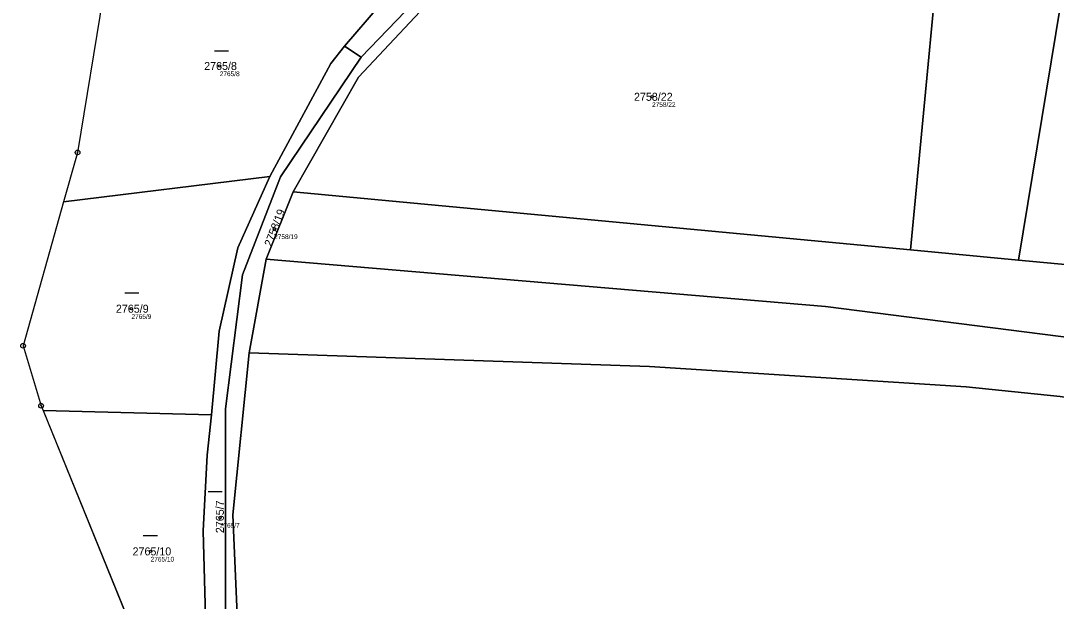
# Model space of a CAD drawing. Extents: x -739214 to -733252, y -1147612 to -1142842.
# Drawn here: x -738787.4 to -738567.4, y -1144355 to -1144231.8 of the extents above; entities that cross this region are included whole.
import ezdxf

# ---------------------------------------------------------------- set-up
doc = ezdxf.new("R2010")
doc.units = 0
for name, color, linetype in [('Definiční body', 7, 'Continuous'), ('Hranice parcel', 7, 'Continuous'), ('Parcelní čísla', 7, 'Continuous'), ('Polygon ku', 7, 'Continuous'), ('Polygon parcely', 7, 'Continuous'), ('Značky bodu BP', 7, 'Continuous'), ('Značky kultur', 7, 'Continuous')]:
    doc.layers.add(name, color=color, linetype=linetype)

msp = doc.modelspace()

# ---------------------------------------------------------------- linework, layer by layer
at = {"layer": 'Definiční body'}
for centre in [(-738745.09, -1144241.38), (-738653.27, -1144247.92), (-738733.53, -1144275.95), (-738763.84, -1144292.89), (-738745.07, -1144337.2), (-738759.77, -1144344.38)]:
    msp.add_circle(centre, 0.25, dxfattribs=at)
at = {"layer": 'Hranice parcel'}
for p, q in [((-738711.14, -1144228.53), (-738718.62, -1144237.17)), ((-738718.62, -1144237.17), (-738715.02, -1144239.51)), ((-738778.25, -1144270.22), (-738734.47, -1144264.86)), ((-738735.23, -1144282.35), (-738729.51, -1144268.12)), ((-738729.51, -1144268.12), (-738598.34, -1144280.41)), ((-738778.25, -1144270.22), (-738786.87, -1144300.76)), ((-738598.34, -1144280.41), (-738575.42, -1144282.56)), ((-738738.82, -1144302.23), (-738735.23, -1144282.35)), ((-738575.42, -1144282.56), (-738557.93, -1144284.19)), ((-738782.62, -1144314.52), (-738746.88, -1144315.43)), ((-738782.62, -1144314.52), (-738764.08, -1144360.02))]:
    msp.add_line(p, q, dxfattribs=at)
for points in [[(-738575.42, -1144282.56), (-738563.56, -1144210.38), (-738538.66, -1144091.78)], [(-738715.02, -1144239.51), (-738686.98, -1144210.3), (-738640.79, -1144166.84), (-738583.86, -1144128.46)], [(-738746.25, -1144205.75), (-738769.88, -1144226.42), (-738775.29, -1144259.73)], [(-738729.51, -1144268.12), (-738715.65, -1144243.76), (-738697.12, -1144224.03), (-738685.65, -1144212.62)], [(-738598.34, -1144280.41), (-738592.87, -1144222.29), (-738675.34, -1144213.49)], [(-738718.62, -1144237.17), (-738721.53, -1144240.85), (-738734.47, -1144264.86)], [(-738715.02, -1144239.51), (-738732.18, -1144264.87), (-738740.28, -1144285.73), (-738743.89, -1144314.16), (-738743.87, -1144375.73)], [(-738775.29, -1144259.73), (-738775.51, -1144260.53), (-738778.25, -1144270.22)], [(-738734.47, -1144264.86), (-738741.22, -1144279.97), (-738745.22, -1144297.67), (-738746.88, -1144315.43)], [(-738735.23, -1144282.35), (-738616.44, -1144292.45), (-738516.99, -1144305.07), (-738441.34, -1144319.86), (-738375.62, -1144334.3), (-738332.46, -1144344.67)], [(-738786.87, -1144300.76), (-738783.05, -1144313.46), (-738782.62, -1144314.52)], [(-738741.37, -1144357.79), (-738742.31, -1144336.61), (-738738.82, -1144302.23)], [(-738738.82, -1144302.23), (-738653.84, -1144305.16), (-738586.54, -1144309.47), (-738566.57, -1144311.53), (-738524.78, -1144317.73), (-738484.2, -1144325.47), (-738327.99, -1144359.59), (-738267.04, -1144371.3), (-738214.93, -1144377.81), (-738095.97, -1144389), (-738073.34, -1144386.23), (-738041.83, -1144388.81), (-738004.8, -1144395.36), (-737972.87, -1144385.13), (-737933.2, -1144398.14)], [(-738746.88, -1144315.43), (-738747.8, -1144323.99), (-738748.62, -1144339.99), (-738747.63, -1144376.34)]]:
    msp.add_lwpolyline(points, dxfattribs=at)
at = {"layer": 'Polygon ku'}
msp.add_lwpolyline([(-738616.13, -1144063.28), (-738648.1, -1144083.66), (-738648.65, -1144084.01), (-738676.28, -1144101.39), (-738707.02, -1144120.72), (-738737.58, -1144139.93), (-738753.77, -1144150.11), (-738761.21, -1144154.79), (-738707.74, -1144176.76), (-738706.74, -1144177.02), (-738709.26, -1144178.7), (-738718.97, -1144185.78), (-738745.71, -1144205.27), (-738746.25, -1144205.75), (-738769.88, -1144226.42), (-738775.29, -1144259.73), (-738775.51, -1144260.53), (-738778.25, -1144270.22), (-738786.87, -1144300.76), (-738783.05, -1144313.46), (-738782.62, -1144314.52), (-738764.08, -1144360.02)], dxfattribs=at)
at = {"layer": 'Polygon parcely'}
for points in [[(-738557.93, -1144284.19), (-738553.97, -1144254.24), (-738546.49, -1144209.14), (-738540.5, -1144177.96), (-738515.61, -1144073.72), (-738524.2, -1144080.05), (-738538.66, -1144091.78), (-738563.56, -1144210.38), (-738575.42, -1144282.56)], [(-738563.56, -1144210.38), (-738538.66, -1144091.78), (-738650.47, -1144189.14), (-738662.72, -1144200.42), (-738675.34, -1144213.49), (-738592.87, -1144222.29), (-738598.34, -1144280.41), (-738575.42, -1144282.56)], [(-738685.65, -1144212.62), (-738670.96, -1144198), (-738643.76, -1144172.41), (-738631.13, -1144162.06), (-738583.86, -1144128.46), (-738640.79, -1144166.84), (-738686.98, -1144210.3), (-738715.02, -1144239.51), (-738732.18, -1144264.87), (-738740.28, -1144285.73), (-738743.89, -1144314.16), (-738743.87, -1144375.73), (-738742.03, -1144375.43), (-738741.69, -1144366.44), (-738741.37, -1144357.79), (-738742.31, -1144336.61), (-738738.82, -1144302.23), (-738735.23, -1144282.35), (-738729.51, -1144268.12), (-738715.65, -1144243.76), (-738697.12, -1144224.03)], [(-738775.51, -1144260.53), (-738778.25, -1144270.22), (-738734.47, -1144264.86), (-738721.53, -1144240.85), (-738718.62, -1144237.17), (-738711.14, -1144228.53), (-738742.64, -1144204.71), (-738746.25, -1144205.75), (-738769.88, -1144226.42), (-738775.29, -1144259.73)], [(-738592.87, -1144222.29), (-738675.34, -1144213.49), (-738685.65, -1144212.62), (-738697.12, -1144224.03), (-738715.65, -1144243.76), (-738729.51, -1144268.12), (-738598.34, -1144280.41)], [(-738743.87, -1144375.73), (-738743.89, -1144314.16), (-738740.28, -1144285.73), (-738732.18, -1144264.87), (-738715.02, -1144239.51), (-738718.62, -1144237.17), (-738721.53, -1144240.85), (-738734.47, -1144264.86), (-738741.22, -1144279.97), (-738745.22, -1144297.67), (-738746.88, -1144315.43), (-738747.8, -1144323.99), (-738748.62, -1144339.99), (-738747.63, -1144376.34)], [(-738782.62, -1144314.52), (-738746.88, -1144315.43), (-738745.22, -1144297.67), (-738741.22, -1144279.97), (-738734.47, -1144264.86), (-738778.25, -1144270.22), (-738786.87, -1144300.76), (-738783.05, -1144313.46)], [(-738516.99, -1144305.07), (-738441.34, -1144319.86), (-738375.62, -1144334.3), (-738332.46, -1144344.67), (-738329.38, -1144330.25), (-738331.33, -1144329.77), (-738346.05, -1144326.18), (-738359.21, -1144322.97), (-738385.79, -1144316.07), (-738411.23, -1144309.47), (-738435.73, -1144303.77), (-738466.06, -1144298.43), (-738495.76, -1144293.2), (-738516.8, -1144290.15), (-738523.79, -1144289.13), (-738543.39, -1144285.74), (-738557.93, -1144284.19), (-738575.42, -1144282.56), (-738598.34, -1144280.41), (-738729.51, -1144268.12), (-738735.23, -1144282.35), (-738616.44, -1144292.45)], [(-738761.91, -1144378.7), (-738747.63, -1144376.34), (-738748.62, -1144339.99), (-738747.8, -1144323.99), (-738746.88, -1144315.43), (-738782.62, -1144314.52), (-738764.08, -1144360.02)]]:
    msp.add_lwpolyline(points, close=True, dxfattribs=at)
for points in [[(-738529.68, -1144078.9), (-738586.54, -1144125.06), (-738589.33, -1144126.92), (-738643.11, -1144162.82), (-738646.45, -1144165.92), (-738689.94, -1144206.33), (-738704.12, -1144220.41), (-738711.14, -1144228.53), (-738718.62, -1144237.17), (-738715.02, -1144239.51), (-738686.98, -1144210.3), (-738640.79, -1144166.84), (-738583.86, -1144128.46), (-738538.66, -1144091.78)], [(-738084.6, -1144374.06), (-738180.34, -1144367.17), (-738223.15, -1144363.36), (-738262.24, -1144358.54), (-738332.46, -1144344.67), (-738375.62, -1144334.3), (-738441.34, -1144319.86), (-738516.99, -1144305.07), (-738616.44, -1144292.45), (-738735.23, -1144282.35), (-738738.82, -1144302.23), (-738653.84, -1144305.16), (-738586.54, -1144309.47), (-738566.57, -1144311.53), (-738524.78, -1144317.73), (-738484.2, -1144325.47), (-738327.99, -1144359.59), (-738267.04, -1144371.3), (-738214.93, -1144377.81), (-738095.97, -1144389)], [(-738095.97, -1144389), (-738214.93, -1144377.81), (-738267.04, -1144371.3), (-738327.99, -1144359.59), (-738484.2, -1144325.47), (-738524.78, -1144317.73), (-738566.57, -1144311.53), (-738586.54, -1144309.47), (-738653.84, -1144305.16), (-738738.82, -1144302.23), (-738742.31, -1144336.61), (-738741.37, -1144357.79), (-738624.05, -1144362.39), (-738594.35, -1144364.65), (-738557.38, -1144368.77), (-738518.7, -1144375.14), (-738452.18, -1144389.24), (-738371.23, -1144407.83), (-738313.52, -1144419.99), (-738272.81, -1144429.85), (-738256.44, -1144428.26), (-738214.14, -1144433.54), (-738072.79, -1144444.03)]]:
    msp.add_lwpolyline(points, dxfattribs=at)
at = {"layer": 'Značky bodu BP'}
for centre, radius in [((-738775.29, -1144259.73), 0.5), ((-738775.29, -1144259.73), 0.0303), ((-738786.87, -1144300.76), 0.5), ((-738786.87, -1144300.76), 0.0303), ((-738783.05, -1144313.46), 0.5), ((-738783.05, -1144313.46), 0.0303)]:
    msp.add_circle(centre, radius, dxfattribs=at)
at = {"layer": 'Značky kultur'}
for p, q in [((-738746.24, -1144238.16), (-738743.24, -1144238.16)), ((-738765.28, -1144289.53), (-738762.28, -1144289.53)), ((-738747.55, -1144331.64), (-738744.55, -1144331.64)), ((-738761.33, -1144341.02), (-738758.33, -1144341.02))]:
    msp.add_line(p, q, dxfattribs=at)

# ---------------------------------------------------------------- texts
at = {"layer": 'Definiční body'}
for s, p in [('2765/8', (-738745.09, -1144243.54)), ('2758/22', (-738653.27, -1144250.08)), ('2758/19', (-738733.53, -1144278.11)), ('2765/9', (-738763.84, -1144295.05)), ('2765/7', (-738745.07, -1144339.36)), ('2765/10', (-738759.77, -1144346.54))]:
    msp.add_text(s, height=1, dxfattribs=at).set_placement(p)
at = {"layer": 'Parcelní čísla'}
for s, p in [('2765/8', (-738748.4, -1144242.23)), ('2758/22', (-738657.11, -1144248.77)), ('2765/9', (-738767.15, -1144293.74)), ('2765/10', (-738763.61, -1144345.23))]:
    msp.add_text(s, height=1.7, dxfattribs=at).set_placement(p)
for s, rotation, p in [('2758/19', 69, (-738734.11, -1144279.84)), ('2765/7', 90, (-738744.22, -1144340.51))]:
    msp.add_text(s, height=1.7, rotation=rotation, dxfattribs=at).set_placement(p)

doc.saveas('drawing.dxf')
